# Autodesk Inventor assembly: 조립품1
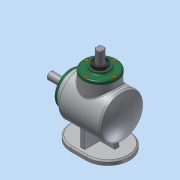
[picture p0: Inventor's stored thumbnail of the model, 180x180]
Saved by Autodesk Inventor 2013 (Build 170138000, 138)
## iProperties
Created: 2016-04
Part Number: 조립품1
Document SubType Name: Assembly
Designer: dgall
Author: dgall
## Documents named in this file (14)
- C:\Users\dgall\Desktop\460407V1013\조립품1.iam
- C:\Users\dgall\Desktop\460407V1013\본체.ipt
- C:\Users\dgall\Desktop\460407V1013\메인 축.ipt
- 메인 축.ipt
- C:\Users\dgall\Desktop\460407V1013\베어링 6203.ipt
- C:\Users\dgall\Desktop\460407V1013\오일실 17 32 8.ipt
- C:\Users\dgall\Desktop\460407V1013\커버.ipt
- C:\Users\dgall\Desktop\460407V1013\서브 축.ipt
- 서브 축.ipt
- C:\Users\dgall\Desktop\460407V1013\키 5x5.ipt
- C:\Users\dgall\Desktop\460407V1013\키 4x4.ipt
- C:\Users\dgall\Desktop\460407V1013\메인 베벨기어.ipt
- C:\Users\dgall\Desktop\460407V1013\서브 베벨기어.ipt
- C:\Users\dgall\Desktop\460407V1013\M4.ipt
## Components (8 placed, 1 different names)
1. M4:1
2. M4:3
3. M4:4
4. M4:5
5. M4:2
6. M4:6
7. M4:7
8. M4:8
